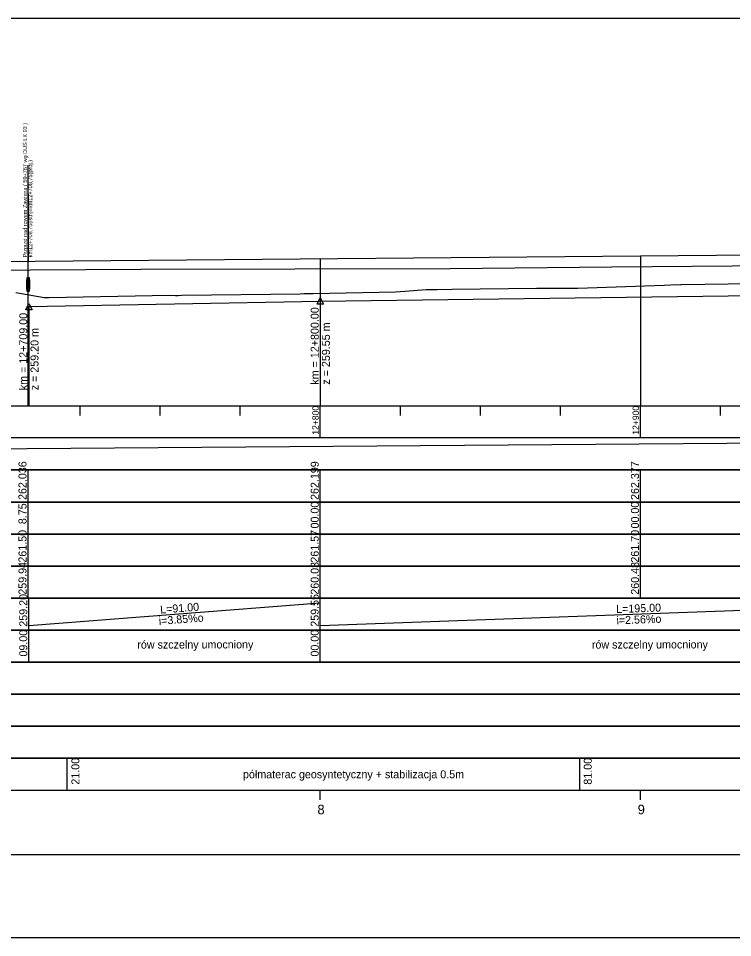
# Model space of a CAD drawing. Extents: x 6445630 to 6518227, y 5499240 to 5511716.
# Drawn here: x 6457336.9 to 6457560, y 5506751.3 to 5507038.3 of the extents above; entities that cross this region are included whole.
import ezdxf

# ---------------------------------------------------------------- set-up
doc = ezdxf.new("R2010")
doc.units = 0
for name, color, linetype in [('TOR_PROF-obiekty+opisy', 7, 'Continuous'), ('TOR_PROF-opisy pomocnicze', 7, 'Continuous'), ('TOR_PROF-rowy otwarte', 7, 'Continuous'), ('TOR_PROF-tabelka-geometria T1', 7, 'Continuous'), ('TOR_PROF-tabelka-kilometracja', 7, 'Continuous'), ('TOR_PROF-tabelka-odleglosci T1', 7, 'Continuous'), ('TOR_PROF-tabelka-pochylenia proj T1', 7, 'Continuous'), ('TOR_PROF-tabelka-rodzaj rowu T1', 7, 'Continuous'), ('TOR_PROF-tabelka-rowyT1', 7, 'Continuous'), ('TOR_PROF-tabelka-rurociagi T1', 7, 'Continuous'), ('TOR_PROF-tabelka-rzedne istn T1', 7, 'Continuous'), ('TOR_PROF-tabelka-rzedne proj T1', 7, 'Continuous'), ('TOR_PROF-tabelka-teren istniejacy T1', 7, 'Continuous'), ('TOR_PROF-tabelka-warstwa ochronna T1', 7, 'Continuous'), ('TOR_PROF-tor istniejacy T2', 7, 'Continuous'), ('TOR_PROF-tor projektowany', 7, 'Continuous'), ('TOR_PROF-uklad odniesienia', 7, 'Continuous'), ('TOR_PROF-warstwa ochronna', 7, 'Continuous'), ('TOR_RAMKI-dodatkowe3', 7, 'Continuous'), ('TOR_RAMKI-MASKA WYCIECIA', 7, 'Continuous')]:
    doc.layers.add(name, color=color, linetype=linetype)

msp = doc.modelspace()

# ---------------------------------------------------------------- linework, layer by layer
at = {"layer": 'TOR_PROF-obiekty+opisy'}
for p, q in [((6457339.96, 5506917.3), (6457339.96, 5506992.48)), ((6457339.96, 5506983.48), (6457339.96, 5506962.48))]:
    msp.add_line(p, q, dxfattribs=at)
for points in [[(6457340.44, 5506957.26), (6457339.52, 5506957.26), (6457339.52, 5506953.18), (6457340.44, 5506953.18)], [(6457340.36, 5506956.72), (6457339.61, 5506956.72), (6457339.61, 5506953.72), (6457340.36, 5506953.72)]]:
    msp.add_lwpolyline(points, close=True, dxfattribs=at)
for points in [[(6457340.44, 5506953.18), (6457340.44, 5506957.26), (6457339.52, 5506957.26), (6457339.52, 5506953.18), (6457340.44, 5506953.18)], [(6457340.36, 5506953.72), (6457339.61, 5506953.72), (6457339.61, 5506956.72), (6457340.36, 5506956.72), (6457340.36, 5506953.72)]]:
    msp.add_lwpolyline(points, dxfattribs=at)
at = {"layer": 'TOR_PROF-opisy pomocnicze'}
for p, q in [((6457340.21, 5506948.3), (6457340.21, 5506921.3)), ((6457431.21, 5506950.05), (6457431.21, 5506923.05))]:
    msp.add_line(p, q, dxfattribs=at)
for points in [[(6457431.21, 5506951.05), (6457432.21, 5506949.05), (6457430.21, 5506949.05)], [(6457340.21, 5506949.3), (6457341.21, 5506947.3), (6457339.21, 5506947.3)]]:
    msp.add_lwpolyline(points, close=True, dxfattribs=at)
at = {"layer": 'TOR_PROF-rowy otwarte'}
for p, q in [((6457431.21, 5506950.05), (6457626.21, 5506952.55)), ((6457340.21, 5506948.3), (6457431.21, 5506950.05))]:
    msp.add_line(p, q, dxfattribs=at)
for points in [[(6457340.21, 5506948.3), (6457340.21, 5506922.3), (6457340.21, 5506917.3), (6457340.21, 5506917.3)], [(6457431.21, 5506950.05), (6457431.21, 5506922.3), (6457431.21, 5506917.3), (6457431.21, 5506917.3)]]:
    msp.add_lwpolyline(points, dxfattribs=at)
at = {"layer": 'TOR_PROF-tabelka-geometria T1'}
for points in [[(6452735.25, 5506777.3), (6458247.17, 5506777.3), (6458247.17, 5506779.97), (6458376.27, 5506779.97), (6458376.27, 5506777.3), (6458396.27, 5506777.3), (6458396.27, 5506774.64), (6458525.37, 5506774.64), (6458525.37, 5506777.3), (6458723.83, 5506777.3), (6458723.83, 5506777.3), (6458758.83, 5506774.64), (6458758.83, 5506774.64), (6458827.61, 5506774.64), (6458827.61, 5506774.64), (6458862.61, 5506777.3), (6458862.61, 5506777.3), (6458862.61, 5506777.3), (6458862.61, 5506777.3), (6458897.61, 5506779.97), (6458897.61, 5506779.97), (6458966.4, 5506779.97), (6458966.4, 5506779.97), (6459001.4, 5506777.3)], [(6452331.21, 5506777.3), (6459531.21, 5506777.3)]]:
    msp.add_lwpolyline(points, dxfattribs=at)
at = {"layer": 'TOR_PROF-tabelka-kilometracja'}
for points in [[(6457431.21, 5506794.3), (6457431.21, 5506797.3)], [(6457531.21, 5506794.3), (6457531.21, 5506797.3)]]:
    msp.add_lwpolyline(points, dxfattribs=at)
at = {"layer": 'TOR_PROF-tabelka-odleglosci T1'}
msp.add_lwpolyline([(6452331.21, 5506877.3), (6459531.21, 5506877.3), (6459531.21, 5506887.3), (6452331.21, 5506887.3)], close=True, dxfattribs=at)
for points in [[(6457339.96, 5506877.3), (6457339.96, 5506887.3)], [(6457431.21, 5506877.3), (6457431.21, 5506887.3)], [(6457531.21, 5506877.3), (6457531.21, 5506887.3)]]:
    msp.add_lwpolyline(points, dxfattribs=at)
at = {"layer": 'TOR_PROF-tabelka-pochylenia proj T1'}
msp.add_lwpolyline([(6452331.21, 5506897.3), (6459531.21, 5506897.3), (6459531.21, 5506907.3), (6452331.21, 5506907.3)], close=True, dxfattribs=at)
msp.add_lwpolyline([(6456656.74, 5506898.8), (6457571.74, 5506905.8)], dxfattribs=at)
at = {"layer": 'TOR_PROF-tabelka-rodzaj rowu T1'}
for points in [[(6452331.21, 5506837.3), (6459531.21, 5506837.3), (6459531.21, 5506847.3), (6452331.21, 5506847.3)], [(6452331.21, 5506817.3), (6459531.21, 5506817.3), (6459531.21, 5506827.3), (6452331.21, 5506827.3)]]:
    msp.add_lwpolyline(points, close=True, dxfattribs=at)
for points in [[(6457340.21, 5506837.3), (6457340.21, 5506847.3)], [(6457431.21, 5506837.3), (6457431.21, 5506847.3)]]:
    msp.add_lwpolyline(points, dxfattribs=at)
at = {"layer": 'TOR_PROF-tabelka-rowyT1'}
msp.add_lwpolyline([(6452331.21, 5506847.3), (6459531.21, 5506847.3), (6459531.21, 5506857.3), (6452331.21, 5506857.3)], close=True, dxfattribs=at)
for points in [[(6457340.21, 5506847.3), (6457340.21, 5506857.3)], [(6457340.21, 5506848.8), (6457431.21, 5506855.8)], [(6457431.21, 5506847.3), (6457431.21, 5506857.3)], [(6457431.21, 5506848.8), (6457626.21, 5506855.8)]]:
    msp.add_lwpolyline(points, dxfattribs=at)
at = {"layer": 'TOR_PROF-tabelka-rurociagi T1'}
msp.add_lwpolyline([(6452331.21, 5506827.3), (6459531.21, 5506827.3), (6459531.21, 5506837.3), (6452331.21, 5506837.3)], close=True, dxfattribs=at)
at = {"layer": 'TOR_PROF-tabelka-rzedne istn T1'}
msp.add_lwpolyline([(6452331.21, 5506867.3), (6459531.21, 5506867.3), (6459531.21, 5506877.3), (6452331.21, 5506877.3)], close=True, dxfattribs=at)
for points in [[(6457339.96, 5506867.3), (6457339.96, 5506877.3)], [(6457431.21, 5506867.3), (6457431.21, 5506877.3)], [(6457531.21, 5506867.3), (6457531.21, 5506877.3)], [(6457339.96, 5506857.3), (6457339.96, 5506867.3)], [(6457339.96, 5506857.3), (6457339.96, 5506867.3)], [(6457339.96, 5506857.3), (6457339.96, 5506867.3)], [(6457431.21, 5506857.3), (6457431.21, 5506867.3)], [(6457431.21, 5506857.3), (6457431.21, 5506867.3)], [(6457431.21, 5506857.3), (6457431.21, 5506867.3)], [(6457531.21, 5506857.3), (6457531.21, 5506867.3)], [(6457531.21, 5506857.3), (6457531.21, 5506867.3)], [(6457531.21, 5506857.3), (6457531.21, 5506867.3)]]:
    msp.add_lwpolyline(points, dxfattribs=at)
at = {"layer": 'TOR_PROF-tabelka-rzedne proj T1'}
msp.add_lwpolyline([(6452331.21, 5506887.3), (6459531.21, 5506887.3), (6459531.21, 5506897.3), (6452331.21, 5506897.3)], close=True, dxfattribs=at)
for points in [[(6457339.96, 5506887.3), (6457339.96, 5506897.3)], [(6457431.21, 5506887.3), (6457431.21, 5506897.3)], [(6457531.21, 5506887.3), (6457531.21, 5506897.3)]]:
    msp.add_lwpolyline(points, dxfattribs=at)
at = {"layer": 'TOR_PROF-tabelka-teren istniejacy T1'}
msp.add_lwpolyline([(6452331.21, 5506857.3), (6459531.21, 5506857.3), (6459531.21, 5506867.3), (6452331.21, 5506867.3)], close=True, dxfattribs=at)
msp.add_lwpolyline([(6452331.21, 5506857.3), (6459531.21, 5506857.3), (6459531.21, 5506867.3), (6452331.21, 5506867.3)], close=True, dxfattribs=at)
msp.add_lwpolyline([(6452331.21, 5506857.3), (6459531.21, 5506857.3), (6459531.21, 5506867.3), (6452331.21, 5506867.3)], close=True, dxfattribs=at)
at = {"layer": 'TOR_PROF-tabelka-warstwa ochronna T1'}
msp.add_lwpolyline([(6452331.21, 5506807.3), (6459531.21, 5506807.3), (6459531.21, 5506817.3), (6452331.21, 5506817.3)], close=True, dxfattribs=at)
at = {"layer": 'TOR_PROF-tor istniejacy T2'}
msp.add_lwpolyline([(6457323.35, 5506959.65), (6457375.16, 5506960.05), (6457423.21, 5506960.15), (6457471.72, 5506960.25), (6457522.28, 5506960.7), (6457572.54, 5506961.2), (6457622.63, 5506961.85), (6457672.41, 5506962.5), (6457722.46, 5506962.7), (6457771.97, 5506963.05), (6457821.96, 5506963.35), (6457872.05, 5506963.5), (6457922.09, 5506964.15), (6457971.39, 5506964.65), (6458022.49, 5506965.3), (6458072.79, 5506965.2), (6458106.04, 5506965.15), (6458121.32, 5506965.4), (6458171.76, 5506965.1), (6458221.3, 5506964.95), (6458270.72, 5506964.8), (6458321.69, 5506965.05)], dxfattribs=at)
at = {"layer": 'TOR_PROF-tor projektowany'}
msp.add_line((6456656.74, 5506956.4), (6457571.74, 5506964.55), dxfattribs=at)
msp.add_line((6456656.74, 5506956.4), (6457571.74, 5506964.55), dxfattribs=at)
for points in [[(6457431.21, 5506963.3), (6457431.21, 5506922.3), (6457431.21, 5506917.3), (6457431.21, 5506917.3)], [(6457431.21, 5506963.3), (6457431.21, 5506922.3), (6457431.21, 5506917.3), (6457431.21, 5506917.3)], [(6457531.21, 5506964.19), (6457531.21, 5506922.3), (6457531.21, 5506917.3), (6457531.21, 5506917.3)], [(6457531.21, 5506964.19), (6457531.21, 5506922.3), (6457531.21, 5506917.3), (6457531.21, 5506917.3)]]:
    msp.add_lwpolyline(points, dxfattribs=at)
at = {"layer": 'TOR_PROF-uklad odniesienia'}
for p, q in [((6452331.21, 5506917.3), (6459531.21, 5506917.3)), ((6457356.21, 5506914.3), (6457356.21, 5506917.3)), ((6457381.21, 5506914.3), (6457381.21, 5506917.3)), ((6457406.21, 5506914.3), (6457406.21, 5506917.3)), ((6457431.21, 5506907.3), (6457431.21, 5506917.3)), ((6457456.21, 5506914.3), (6457456.21, 5506917.3)), ((6457481.21, 5506914.3), (6457481.21, 5506917.3)), ((6457506.21, 5506914.3), (6457506.21, 5506917.3)), ((6457531.21, 5506907.3), (6457531.21, 5506917.3)), ((6457556.21, 5506914.3), (6457556.21, 5506917.3))]:
    msp.add_line(p, q, dxfattribs=at)
at = {"layer": 'TOR_PROF-warstwa ochronna'}
msp.add_lwpolyline([(6452331.21, 5506797.3), (6459531.21, 5506797.3), (6459531.21, 5506807.3), (6452331.21, 5506807.3)], close=True, dxfattribs=at)
for points in [[(6457352.21, 5506797.3), (6457352.21, 5506807.3)], [(6457512.21, 5506797.3), (6457512.21, 5506807.3)]]:
    msp.add_lwpolyline(points, dxfattribs=at)
at = {"layer": 'TOR_RAMKI-dodatkowe3'}
for p, q in [((6457454.67, 5506952.97), (6457457.55, 5506953.17)), ((6457457.55, 5506953.17), (6457464.22, 5506953.64)), ((6457464.22, 5506953.64), (6457467.64, 5506953.65)), ((6457467.64, 5506953.65), (6457472.43, 5506953.71)), ((6457472.43, 5506953.71), (6457498.72, 5506954.02)), ((6457498.72, 5506954.02), (6457500.44, 5506954.04)), ((6457500.44, 5506954.04), (6457504.4, 5506954.07)), ((6457504.4, 5506954.07), (6457505.57, 5506954.1)), ((6457505.57, 5506954.1), (6457511.59, 5506954.06)), ((6457511.59, 5506954.06), (6457538.59, 5506954.96)), ((6457538.59, 5506954.96), (6457542.69, 5506955.17)), ((6457542.69, 5506955.17), (6457543.57, 5506955.16)), ((6457543.57, 5506955.16), (6457543.89, 5506955.18)), ((6457543.89, 5506955.18), (6457565.97, 5506955.48)), ((6457336.11, 5506952.67), (6457345.02, 5506951.11)), ((6457345.02, 5506951.11), (6457345.1, 5506951.11)), ((6457345.1, 5506951.11), (6457345.83, 5506951.16)), ((6457345.83, 5506951.16), (6457346.46, 5506951.2)), ((6457346.46, 5506951.2), (6457384.1, 5506951.92)), ((6457384.1, 5506951.92), (6457386.03, 5506951.82)), ((6457386.03, 5506951.82), (6457386.78, 5506951.81)), ((6457386.78, 5506951.81), (6457387.93, 5506951.86)), ((6457387.93, 5506951.86), (6457424.95, 5506952.35)), ((6457424.95, 5506952.35), (6457426.02, 5506952.36)), ((6457426.02, 5506952.36), (6457426.56, 5506952.36)), ((6457426.56, 5506952.36), (6457428.93, 5506952.41)), ((6457428.93, 5506952.41), (6457454.65, 5506952.97)), ((6457454.65, 5506952.97), (6457454.66, 5506952.97)), ((6457454.66, 5506952.97), (6457454.67, 5506952.97))]:
    msp.add_line(p, q, dxfattribs=at)
at = {"layer": 'TOR_RAMKI-MASKA WYCIECIA'}
msp.add_lwpolyline([(6455538.23, 5506751.3), (6457588.23, 5506751.3), (6457588.23, 5507038.3), (6455538.23, 5507038.3)], close=True, dxfattribs=at)

# ---------------------------------------------------------------- texts
at = {"layer": 'TOR_PROF-obiekty+opisy'}
for s, p in [('Przpust nad rowem Zawisna ( 59+767 wg DUŚ LK 93 )', (6457339.63, 5506963.71)), ('km12+708,75(istn)=km12+708,75(proj.)', (6457341.24, 5506963.71))]:
    msp.add_text(s, height=1.25, rotation=90, dxfattribs=at).set_placement(p)
at = {"layer": 'TOR_PROF-opisy pomocnicze'}
for s, p in [('km = 12+800.00', (6457430.71, 5506923.95)), ('km = 12+709.00', (6457339.71, 5506922.2)), ('z = 259.55 m', (6457434.21, 5506923.95)), ('z = 259.20 m', (6457343.21, 5506922.2))]:
    msp.add_text(s, height=2.5, rotation=90, dxfattribs=at).set_placement(p)
at = {"layer": 'TOR_PROF-tabelka-kilometracja'}
for s, p in [('8', (6457430.32, 5506789.8)), ('9', (6457530.32, 5506789.8))]:
    msp.add_text(s, height=3, dxfattribs=at).set_placement(p)
at = {"layer": 'TOR_PROF-tabelka-odleglosci T1'}
for s, p in [('00.00', (6457430.71, 5506879.04)), ('00.00', (6457530.71, 5506879.04)), ('8.75', (6457339.46, 5506880.39))]:
    msp.add_text(s, height=2.5, rotation=90, dxfattribs=at).set_placement(p)
at = {"layer": 'TOR_PROF-tabelka-rodzaj rowu T1'}
for s, p in [('09.00', (6457339.71, 5506839.05)), ('00.00', (6457430.71, 5506839.05))]:
    msp.add_text(s, height=2.5, rotation=90, dxfattribs=at).set_placement(p)
at = {"layer": 'TOR_PROF-tabelka-rowyT1'}
for s, rotation, p in [('259.20', 90, (6457339.71, 5506848.37)), ('259.55', 90, (6457430.71, 5506848.36)), ('L=91.00', 4.3987, (6457381.29, 5506852.46)), ('L=195.00', 2.0559, (6457523.62, 5506852.62)), ('i=3.85%o', 4.3987, (6457380.86, 5506848.92)), ('i=2.56%o', 2.0559, (6457523.73, 5506849.12)), ('rów szczelny umocniony', 0.087, (6457374.07, 5506841.54)), ('rów szczelny umocniony', 0.087, (6457516.01, 5506841.54))]:
    msp.add_text(s, height=2.5, rotation=rotation, dxfattribs=at).set_placement(p)
at = {"layer": 'TOR_PROF-tabelka-rzedne istn T1'}
for s, p in [('261.50', (6457339.46, 5506868.37)), ('261.57', (6457430.71, 5506868.37)), ('261.70', (6457530.71, 5506868.37)), ('259.94', (6457339.46, 5506858.37)), ('260.03', (6457430.71, 5506858.37)), ('260.48', (6457530.71, 5506858.36))]:
    msp.add_text(s, height=2.5, rotation=90, dxfattribs=at).set_placement(p)
at = {"layer": 'TOR_PROF-tabelka-rzedne proj T1'}
for s, p in [('262.036', (6457339.46, 5506887.94)), ('262.199', (6457430.71, 5506887.94)), ('262.377', (6457530.71, 5506887.94))]:
    msp.add_text(s, height=2.5, rotation=90, dxfattribs=at).set_placement(p)
at = {"layer": 'TOR_PROF-uklad odniesienia'}
for s, p in [('12+800', (6457430.71, 5506908.32)), ('12+900', (6457530.71, 5506908.32))]:
    msp.add_text(s, height=2, rotation=90, dxfattribs=at).set_placement(p)
at = {"layer": 'TOR_PROF-warstwa ochronna'}
for s, p in [('21.00', (6457355.97, 5506799.05)), ('81.00', (6457515.97, 5506799.05))]:
    msp.add_text(s, height=2.5, rotation=90, dxfattribs=at).set_placement(p)
msp.add_text('półmaterac geosyntetyczny + stabilizacja 0.5m', height=2.5, dxfattribs=at).set_placement((6457407.07, 5506801.05))

doc.saveas('drawing.dxf')
